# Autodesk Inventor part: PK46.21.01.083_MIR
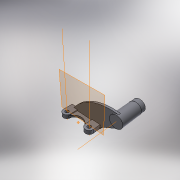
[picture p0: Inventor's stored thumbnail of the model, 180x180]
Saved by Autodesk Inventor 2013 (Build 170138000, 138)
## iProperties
Created: 2005-03
Part Number: PK46.21.01.083_MIR
Material: Steel, Mild
Document SubType Name: Modeling
Designer: salex
Manufacturer: Standard
Standards Organization: Custom
Density: 7.86 g/cm^3
Mass: 4464.91 g
Surface Area: 799.794 cm^2
Volume: 568.055 cm^3
Author: salex
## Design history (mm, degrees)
derived "PK46.21.01.083.ipt"
  node "РабПлоскость12_1"
  node "РабОсь11_1"
  node "РабОсь12_1"
  node "РабОсь13_1"
  node "РабТочка2_1"
body "Solid1"
feature "Solid1::PK46.21.01.083.ipt"
tag "TaggingFeature3"
body "Solid2"
